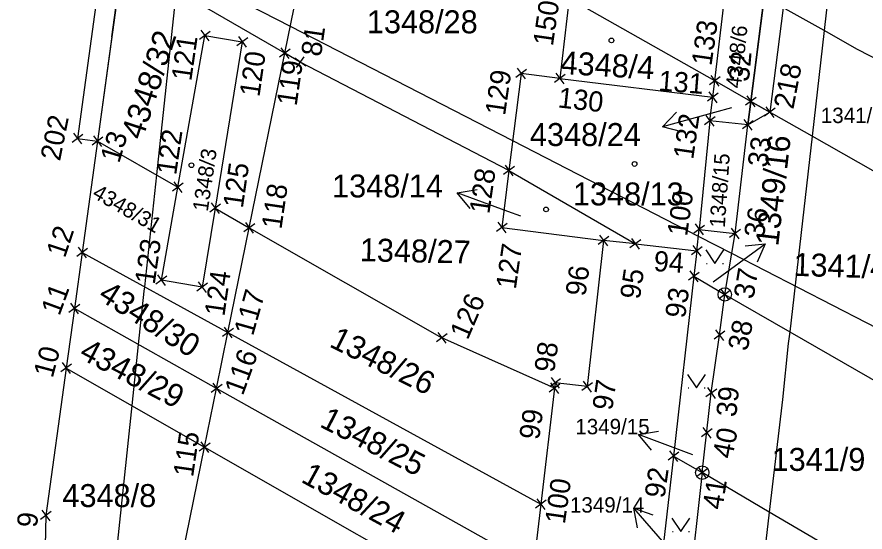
# Model space of a CAD drawing. Extents: x -735036 to -734743, y -1144813 to -1144181.
# Drawn here: x -734895.5 to -734832.6, y -1144606.2 to -1144568.1 of the extents above; entities that cross this region are included whole.
import ezdxf

# ---------------------------------------------------------------- set-up
doc = ezdxf.new("R2010")
doc.units = 0
for name, color, linetype in [('A3_SIT_OBJEKTY_N01', 7, 'Continuous'), ('BPEJ', 7, 'Continuous'), ('Groma (60)', 7, 'Continuous'), ('Katastr_HRANICE DRÁHY', 7, 'Continuous'), ('Katastr_Hranice parcel', 7, 'Continuous'), ('Katastr_Parcelní čísla', 7, 'Continuous'), ('Katastr_Slučkované čáry', 7, 'Continuous'), ('Katastr_Značky kultur', 7, 'Continuous'), ('ZÁBORY_dočasné', 7, 'Continuous')]:
    doc.layers.add(name, color=color, linetype=linetype)

# ---------------------------------------------------------------- blocks, each defined once
blk = doc.blocks.new('POINT_DISPLAY')
for p, q in [((-0.35, -0.35), (0.35, 0.35)), ((-0.35, 0.35), (0.35, -0.35))]:
    blk.add_line(p, q)

msp = doc.modelspace()

# ---------------------------------------------------------------- linework, layer by layer
at = {"layer": 'A3_SIT_OBJEKTY_N01'}
for points in [[(-734888.44, -1144569.554), (-734887.65, -1144563.8), (-734885.58, -1144548.75), (-734874.6, -1144550.79), (-734868.084, -1144506.936)], [(-734833.069, -1144512.138), (-734834.23, -1144521.36), (-734836.63, -1144539.96), (-734838.79, -1144556.7), (-734840.06, -1144566.59), (-734840.228, -1144567.714), (-734841.06, -1144574.32)]]:
    msp.add_lwpolyline(points, dxfattribs=at)
at = {"layer": 'BPEJ'}
msp.add_lwpolyline([(-734830, -1144592), (-734842.48, -1144585.59), (-734843.64, -1144584.99), (-734844.95, -1144584.32), (-734858.71, -1144577.24), (-734875.19, -1144568.77), (-734883.5, -1144564.5), (-734883.67, -1144566.1), (-734885.13, -1144579.76), (-734886.01, -1144588.05), (-734886.05, -1144588.39), (-734886.47, -1144592.33), (-734886.95, -1144596.85), (-734888.29, -1144609.47)], dxfattribs=at)
at = {"layer": 'Katastr_HRANICE DRÁHY'}
for points in [[(-734887.65, -1144563.8), (-734889.5, -1144577.27)], [(-734841.06, -1144574.32), (-734840.06, -1144566.59)], [(-734841.28, -1144576.06), (-734841.06, -1144574.32)], [(-734842.23, -1144584.11), (-734841.28, -1144576.06)], [(-734889.5, -1144577.27), (-734890.64, -1144585.51)], [(-734858.99, -1144579.44), (-734859.52, -1144583.67)], [(-734858.99, -1144579.44), (-734849.62, -1144584.88)], [(-734859.52, -1144583.67), (-734851.98, -1144584.62)], [(-734842.99, -1144588.62), (-734842.23, -1144584.11)], [(-734849.62, -1144584.88), (-734851.98, -1144584.62)], [(-734890.64, -1144585.51), (-734891.21, -1144589.67)], [(-734843.38, -1144591.64), (-734842.99, -1144588.62)], [(-734891.21, -1144589.67), (-734891.82, -1144594.07)], [(-734843.99, -1144595.92), (-734843.38, -1144591.64)], [(-734891.82, -1144594.07), (-734893.32, -1144605)], [(-734844.66, -1144601.82), (-734843.99, -1144595.92)], [(-734844.66, -1144601.82), (-734845.64, -1144610.44)], [(-734893.32, -1144605), (-734893.39, -1144608.37)]]:
    msp.add_lwpolyline(points, dxfattribs=at)
at = {"layer": 'Katastr_Hranice parcel'}
for points in [[(-734875.6, -1144570.76), (-734872.67, -1144556.37)], [(-734875.6, -1144570.76), (-734887.65, -1144563.8)], [(-734843.73, -1144572.8), (-734842.81, -1144565.04)], [(-734854.52, -1144566.67), (-734855.22, -1144572.62)], [(-734843.73, -1144572.8), (-734854.52, -1144566.67)], [(-734835.63, -1144569.08), (-734840.06, -1144566.59)], [(-734833.15, -1144570.47), (-734835.63, -1144569.08)], [(-734883.54, -1144580.67), (-734881.54, -1144569.44)], [(-734881.54, -1144569.44), (-734878.76, -1144569.92)], [(-734878.76, -1144569.92), (-734880.78, -1144582.24)], [(-734828.72, -1144572.76), (-734833.15, -1144570.47)], [(-734878.24, -1144583.69), (-734875.6, -1144570.76)], [(-734874.46, -1144571.42), (-734875.6, -1144570.76)], [(-734858.99, -1144579.44), (-734874.46, -1144571.42)], [(-734858.08, -1144572.26), (-734858.99, -1144579.44)], [(-734855.22, -1144572.62), (-734858.08, -1144572.26)], [(-734855.22, -1144572.62), (-734843.88, -1144574.02)], [(-734843.88, -1144574.02), (-734843.73, -1144572.8)], [(-734841.06, -1144574.32), (-734843.73, -1144572.8)], [(-734844.09, -1144575.76), (-734843.88, -1144574.02)], [(-734836.52, -1144576.89), (-734841.06, -1144574.32)], [(-734844.09, -1144575.76), (-734844.89, -1144583.8)], [(-734841.28, -1144576.06), (-734844.09, -1144575.76)], [(-734889.5, -1144577.27), (-734883.54, -1144580.67)], [(-734829.64, -1144580.8), (-734836.52, -1144576.89)], [(-734884.76, -1144587.57), (-734883.54, -1144580.67)], [(-734880.78, -1144582.24), (-734881.74, -1144588.08)], [(-734880.78, -1144582.24), (-734878.24, -1144583.69)], [(-734879.82, -1144591.44), (-734878.24, -1144583.69)], [(-734878.24, -1144583.69), (-734863.97, -1144591.84)], [(-734845.07, -1144585.39), (-734844.89, -1144583.8)], [(-734844.89, -1144583.8), (-734842.23, -1144584.11)], [(-734851.98, -1144584.62), (-734853.19, -1144595.45)], [(-734849.62, -1144584.88), (-734845.07, -1144585.39)], [(-734890.64, -1144585.51), (-734879.82, -1144591.44)], [(-734845.07, -1144585.39), (-734845.28, -1144587.28)], [(-734845.28, -1144587.28), (-734846.8, -1144600.6)], [(-734845.28, -1144587.28), (-734842.99, -1144588.62)], [(-734881.74, -1144588.08), (-734884.76, -1144587.57)], [(-734842.99, -1144588.62), (-734838.18, -1144591.38)], [(-734880.66, -1144595.58), (-734891.21, -1144589.67)], [(-734880.66, -1144595.58), (-734879.82, -1144591.44)], [(-734879.82, -1144591.44), (-734856.63, -1144604.15)], [(-734855.61, -1144595.57), (-734863.97, -1144591.84)], [(-734838.18, -1144591.38), (-734831.24, -1144595.37)], [(-734891.82, -1144594.07), (-734881.55, -1144599.93)], [(-734881.55, -1144599.93), (-734880.66, -1144595.58)], [(-734857.17, -1144608.74), (-734880.66, -1144595.58)], [(-734855.61, -1144595.57), (-734856.63, -1144604.15)], [(-734855.56, -1144595.17), (-734855.61, -1144595.57)], [(-734853.19, -1144595.45), (-734855.56, -1144595.17)], [(-734883.7, -1144610.47), (-734881.55, -1144599.93)], [(-734881.55, -1144599.93), (-734858.79, -1144612.91)], [(-734846.8, -1144600.6), (-734847.79, -1144609.19)], [(-734846.8, -1144600.6), (-734844.66, -1144601.82)], [(-734839.69, -1144604.74), (-734844.66, -1144601.82)], [(-734856.63, -1144604.15), (-734857.17, -1144608.74)], [(-734832.82, -1144608.77), (-734839.69, -1144604.74)]]:
    msp.add_lwpolyline(points, dxfattribs=at)
at = {"layer": 'Katastr_Parcelní čísla'}
for p, q in [((-734842.5, -1144574.79), (-734843.76, -1144575.14)), ((-734846.165, -1144576.578), (-734847.617, -1144576.2)), ((-734861.873, -1144582.25), (-734862.833, -1144581.096)), ((-734858.12, -1144582.83), (-734859.08, -1144582.48)), ((-734841.483, -1144585.031), (-734839.991, -1144584.869)), ((-734843.85, -1144587.69), (-734843.22, -1144587.23)), ((-734848.422, -1144600.148), (-734849.377, -1144598.991)), ((-734845.36, -1144600.49), (-734845.63, -1144600.39)), ((-734849.452, -1144605.917), (-734849.734, -1144604.442))]:
    msp.add_line(p, q, dxfattribs=at)
for points in [[(-734843.76, -1144575.14), (-734847.617, -1144576.2), (-734846.562, -1144575.132)], [(-734859.08, -1144582.48), (-734862.833, -1144581.096), (-734861.354, -1144580.842)], [(-734843.22, -1144587.23), (-734839.991, -1144584.869), (-734840.598, -1144586.242)], [(-734845.63, -1144600.39), (-734849.377, -1144598.991), (-734847.897, -1144598.743)], [(-734847.12, -1144607.47), (-734849.734, -1144604.442), (-734848.317, -1144604.936)]]:
    msp.add_lwpolyline(points, dxfattribs=at)
at = {"layer": 'Katastr_Slučkované čáry'}
for points in [[(-734834.48, -1144559.05), (-734835.63, -1144569.08)], [(-734835.63, -1144569.08), (-734836.52, -1144576.89)], [(-734836.52, -1144576.89), (-734838.18, -1144591.38)], [(-734838.18, -1144591.38), (-734838.28, -1144592.26)], [(-734838.28, -1144592.26), (-734838.72, -1144596.41)], [(-734838.72, -1144596.41), (-734839.69, -1144604.74)], [(-734839.69, -1144604.74), (-734840.68, -1144613.32)]]:
    msp.add_lwpolyline(points, dxfattribs=at)
at = {"layer": 'Katastr_Značky kultur'}
for p, q in [((-734844.39, -1144585.325), (-734843.72, -1144586.33)), ((-734843.72, -1144586.33), (-734843.05, -1144585.325)), ((-734844.356, -1144586.33), (-734844.29, -1144586.33)), ((-734843.15, -1144586.33), (-734843.084, -1144586.33)), ((-734843.04, -1144588.62), (-734842.94, -1144588.62)), ((-734845.75, -1144594.545), (-734845.08, -1144595.55)), ((-734845.08, -1144595.55), (-734844.41, -1144594.545)), ((-734845.716, -1144595.55), (-734845.65, -1144595.55)), ((-734844.51, -1144595.55), (-734844.443, -1144595.55)), ((-734844.71, -1144601.82), (-734844.61, -1144601.82)), ((-734846.91, -1144605.185), (-734846.24, -1144606.19)), ((-734846.24, -1144606.19), (-734845.57, -1144605.185)), ((-734846.877, -1144606.19), (-734846.81, -1144606.19)), ((-734845.671, -1144606.19), (-734845.603, -1144606.19))]:
    msp.add_line(p, q, dxfattribs=at)
for centre, radius in [((-734851.39, -1144569.81), 0.175), ((-734882.53, -1144579.05), 0.175), ((-734849.68, -1144578.96), 0.175), ((-734856.24, -1144582.33), 0.175), ((-734842.99, -1144588.62), 0.499), ((-734844.66, -1144601.82), 0.499)]:
    msp.add_circle(centre, radius, dxfattribs=at)
at = {"layer": 'ZÁBORY_dočasné'}
for p, q in [((-734889.125, -1144563.502), (-734890.986, -1144577.066)), ((-734887.65, -1144563.8), (-734889.5, -1144577.27)), ((-734840.06, -1144566.59), (-734841.06, -1144574.32)), ((-734838.65, -1144567.383), (-734839.651, -1144575.118)), ((-734841.06, -1144574.32), (-734841.28, -1144576.059)), ((-734841.06, -1144574.32), (-734839.651, -1144575.118)), ((-734841.28, -1144576.06), (-734839.651, -1144575.118)), ((-734890.986, -1144577.066), (-734889.5, -1144577.271))]:
    msp.add_line(p, q, dxfattribs=at)

# ---------------------------------------------------------------- block references
at = {"layer": 'Groma (60)'}
for p, rotation in [((-734881.54, -1144569.44), -98.65482414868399), ((-734878.76, -1144569.92), -98.65482414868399), ((-734875.6, -1144570.76), -98.65482414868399), ((-734874.46, -1144571.42), 98.65482414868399), ((-734858.08, -1144572.26), -98.65482414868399), ((-734855.22, -1144572.62), -98.65482414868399), ((-734843.73, -1144572.8), -98.65482414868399), ((-734843.88, -1144574.02), -98.65482414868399), ((-734841.06, -1144574.32), -98.65482414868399), ((-734839.651, -1144575.118), -98.65482414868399), ((-734844.09, -1144575.76), -98.65482414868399), ((-734841.28, -1144576.06), -98.65482414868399), ((-734890.986, -1144577.066), -98.65482414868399), ((-734889.5, -1144577.271), -98.65482414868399), ((-734858.99, -1144579.44), -98.65482414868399), ((-734883.54, -1144580.67), -98.65482414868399), ((-734880.78, -1144582.24), -98.65482414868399), ((-734878.24, -1144583.69), -98.65482414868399), ((-734859.52, -1144583.67), -98.65482414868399), ((-734844.89, -1144583.8), -98.65482414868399), ((-734851.98, -1144584.62), -98.65482414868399), ((-734842.23, -1144584.11), -98.65482414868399), ((-734849.62, -1144584.88), -98.65482414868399), ((-734890.64, -1144585.51), -98.65482414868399), ((-734845.07, -1144585.39), -98.65482414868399), ((-734884.76, -1144587.57), -98.65482414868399), ((-734845.28, -1144587.28), -98.65482414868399), ((-734881.74, -1144588.08), -98.65482414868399), ((-734842.99, -1144588.62), -98.65482414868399), ((-734891.21, -1144589.67), -98.65482414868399), ((-734879.82, -1144591.44), -98.65482414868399), ((-734863.97, -1144591.84), -98.65482414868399), ((-734843.38, -1144591.64), -98.65482414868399), ((-734891.82, -1144594.07), -98.65482414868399), ((-734855.56, -1144595.17), -98.65482414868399), ((-734880.66, -1144595.58), -98.65482414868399), ((-734855.61, -1144595.57), -98.65482414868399), ((-734853.19, -1144595.45), -98.65482414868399), ((-734843.99, -1144595.92), -98.65482414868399), ((-734844.325, -1144598.87), -98.65482414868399), ((-734881.55, -1144599.93), -98.65482414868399), ((-734846.8, -1144600.6), -98.65482414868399), ((-734844.66, -1144601.82), -98.65482414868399), ((-734856.63, -1144604.15), -98.65482414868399), ((-734893.32, -1144605), -98.65482414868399)]:
    msp.add_blockref('POINT_DISPLAY', p, dxfattribs=dict(at, rotation=rotation))

# ---------------------------------------------------------------- texts
for s, rotation, p in [('150', 81.78352, (-734855.736, -1144570.274)), ('133', 81.78352, (-734843.982, -1144571.737)), ('81', 81.78352, (-734872.927, -1144571.054)), ('121', 81.78352, (-734882.543, -1144572.862)), ('120', 81.78352, (-734877.493, -1144574.044)), ('32', 84.58057, (-734841.207, -1144572.903)), ('119', 81.78352, (-734874.736, -1144574.712)), ('218', 79.1342, (-734837.909, -1144574.955)), ('129', 81.78352, (-734859.283, -1144575.421)), ('131', 355.55956, (-734847.943, -1144573.521)), ('130', 353.62031, (-734855.408, -1144574.765)), ('202', 78.50295, (-734892.276, -1144578.795)), ('132', 81.78352, (-734845.334, -1144578.666)), ('13', 73.06869, (-734887.892, -1144578.958)), ('122', 81.78352, (-734883.665, -1144579.826)), ('33', 82.00124, (-734839.831, -1144579.261)), ('125', 81.78352, (-734878.721, -1144582.282)), ('128', 81.78352, (-734860.449, -1144582.708)), ('118', 81.78352, (-734875.86, -1144583.844)), ('100', 81.78352, (-734845.791, -1144584.363)), ('36', 80.44897, (-734840.108, -1144584.508)), ('12', 71.62734, (-734891.91, -1144585.981)), ('123', 81.78352, (-734885.256, -1144587.929)), ('127', 81.78352, (-734858.485, -1144588.288)), ('94', 355.96778, (-734848.297, -1144586.883)), ('96', 81.78352, (-734853.328, -1144588.806)), ('95', 81.78352, (-734849.288, -1144589.034)), ('37', 80.44897, (-734840.868, -1144589.018)), ('124', 81.78352, (-734880.09, -1144590.289)), ('11', 69.82677, (-734892.317, -1144590.264)), ('117', 74.1657, (-734877.969, -1144591.748)), ('126', 66.58923, (-734862.053, -1144592.054)), ('93', 81.78352, (-734845.941, -1144590.441)), ('38', 79.04956, (-734841.31, -1144592.867)), ('98', 81.78352, (-734855.641, -1144594.452)), ('10', 75.07533, (-734892.819, -1144594.863)), ('116', 70.04187, (-734878.722, -1144596.176)), ('97', 81.78352, (-734851.338, -1144597.264)), ('39', 84.32622, (-734842.142, -1144597.736)), ('99', 81.78352, (-734856.761, -1144599.438)), ('40', 78.73656, (-734842.448, -1144600.851)), ('115', 81.78352, (-734882.41, -1144602.197)), ('92', 81.78352, (-734847.461, -1144603.761)), ('100', 81.78352, (-734854.85, -1144605.676)), ('41', 81.107, (-734843.174, -1144604.618)), ('9', 84.72033, (-734893.98, -1144605.929))]:
    msp.add_text(s, height=1.5, rotation=rotation, dxfattribs=at).set_placement(p)
at = {"layer": 'Katastr_Parcelní čísla'}
for s, height, p in [('1348/28', 1.7, (-734869.524, -1144569.28)), ('1341/54', 1.14, (-734835.869, -1144575.93)), ('4348/24', 1.7, (-734857.436, -1144577.63)), ('1348/14', 1.7, (-734872.104, -1144581.44)), ('1348/13', 1.7, (-734854.251, -1144582.03)), ('1349/15', 1.14, (-734854.071, -1144598.98)), ('1341/9', 1.7, (-734839.521, -1144601.69)), ('4348/8', 1.7, (-734892.093, -1144604.37)), ('1349/14', 1.14, (-734854.469, -1144604.78))]:
    msp.add_text(s, height=height, dxfattribs=at).set_placement(p)
for s, height, rotation, p in [('4348/32', 1.7, 71.92764, (-734886.167, -1144577.248)), ('4348/6', 1.14, 83.8845, (-734841.793, -1144573.389)), ('4348/4', 1.7, 356.64444, (-734855.201, -1144572.285)), ('1349/16', 1.7, 83.39346, (-734839.03, -1144585.09)), ('1348/3', 1.14, 81.64926, (-734881.32, -1144582.524)), ('1348/15', 1.14, 86.06448, (-734842.99, -1144583.708)), ('4348/31', 1.14, 330.23547, (-734889.96, -1144581.39)), ('1348/27', 1.7, 358.76061, (-734870.063, -1144586.158)), ('1341/4', 1.7, 358.29018, (-734837.921, -1144587.244)), ('4348/30', 1.7, 327.42684, (-734889.533, -1144588.935)), ('1348/26', 1.7, 333.43497, (-734872.385, -1144592.448)), ('4348/29', 1.7, 332.34471, (-734890.941, -1144593.302)), ('1348/25', 1.7, 332.82063, (-734873.104, -1144598.377)), ('1348/24', 1.7, 331.31088, (-734874.487, -1144602.47))]:
    msp.add_text(s, height=height, rotation=rotation, dxfattribs=at).set_placement(p)

doc.saveas('drawing.dxf')
